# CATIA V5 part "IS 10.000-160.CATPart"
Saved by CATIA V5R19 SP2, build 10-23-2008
Part number: IS 10.000-160
Bounding box of the stored display mesh (mm): x -97.324 to 97.324, y -97.5 to 97.5, z 0 to 480
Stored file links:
  C:\Users\Bora\Desktop\3D Katı model\IS serisi\IS 10.000\IS 10.000-160.CATPart
  C:\Program Files\Dassault Systemes\B19\intel_a\reffiles\standard\MetricThickPitch.txt
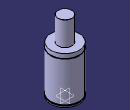
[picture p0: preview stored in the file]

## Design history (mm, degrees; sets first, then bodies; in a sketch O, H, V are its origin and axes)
Body1 (main body)
  Sketch1 on yz-plane, origin (0, 0, 0), H (0, 1, 0), V (0, 0, 1)
    point P1 (97.5, 289)
    point P2 (97.5, 284)
    point P5 (47.5, 479)
    point P7 (47.5, 479)
    point P12 (97.5, 284)
    point P13 (97.5, 289)
    arc A1 centre (97.5, 286.5) radius 2.5 from (97.5, 289) to (97.5, 284) ccw
    line L1 (97.5, 0) -> (97.5, 8)
    line L2 (47.5, 479) -> (47.5, 317)
    arc A2 centre (46.5, 479) radius 1 from (47.5, 479) to (46.5, 480) ccw
    line L3 (93.5, 16) -> (93.5, 8)
    line L4 (97.5, 16) -> (97.5, 284)
    line L5 (97.5, 289) -> (97.5, 317)
    line L6 (46.5, 480) -> (0, 480)
    point P15 (0, 480)
    line L7 (47.5, 317) -> (97.5, 317)
    line L8 (93.5, 16) -> (97.5, 16)
    line L9 (93.5, 8) -> (97.5, 8)
    line L10 (97.5, 0) -> (0, 0)
    coincidence: P15 V, P1 P13, P2 P12, P5 P7
    tangency: L6 A2
    horizontal: L7 H, L8 H, L9 H, L10 H
  Shaft1: profile Sketch1, axis Sketch1.V, angle 360
  Sketch2 on face of Shaft1 from Sketch1.L10, origin (0, 0, 0), H (1, 0, 0), V (0, -1, 0)
    point P1 (60, 0)
    distance P1 V = 60
  Hole1: placed by Sketch2, at (60, 0, 0) direction (0, 0, 1), diameter 10.106, depth 16, threaded "M12", thread diameter 12, thread depth 16, pitch 1.75
  CircPattern1: of Hole1, instances 4, angular step 90, axis from xy-plane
